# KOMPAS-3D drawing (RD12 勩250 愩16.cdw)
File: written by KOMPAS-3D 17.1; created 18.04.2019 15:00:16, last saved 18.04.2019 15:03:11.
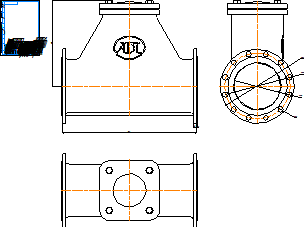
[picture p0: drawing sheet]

Sheet 1: A4, portrait

Title block, sheet 1: name: RD12 Ду250 Ру16; material: Внимание! Данный продукт является объектом авторского права ООО «Торговый Дом АДЛ». / Запрещается изменение, копирование, распространение / (в том числе путем копирования на другие сайты и ресурсы в Интернете) / или любое иное использование информации и объектов без предварительного / согласия правообладателя (ООО «Торговый Дом АДЛ»).; mass: 538,99; sheets: 1; organisation: ООО "Торговый дом АДЛ"; sheet format: A4

Views: Вид 1, Проекционный вид 2, Проекционный вид 3
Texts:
  user
Dimensions and other numbers on the sheet: 19; 3; 724; 460; 355; 400; 250; 28; 1:1; 1; 538,99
